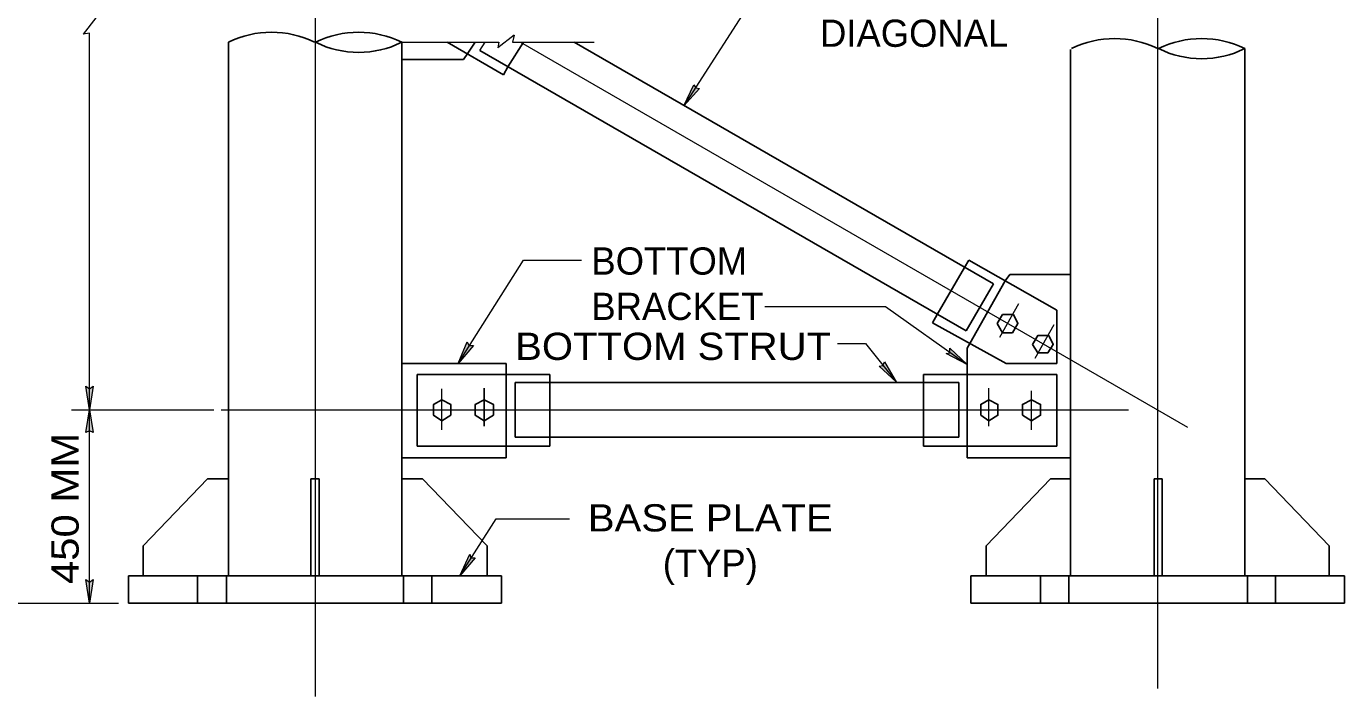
# Model space of a CAD drawing. Extents: x 312601.858 to 312602.699, y 144420.109 to 144420.704.
# Drawn here: x 312601.9345 to 312602.0798, y 144420.3488 to 144420.4227 of the extents above; entities that cross this region are included whole.
import ezdxf
from ezdxf.enums import TextEntityAlignment as Align

# ---------------------------------------------------------------- set-up
doc = ezdxf.new("R2010")
doc.units = 0
doc.header["$LTSCALE"] = 0.0012
for name, pattern in [('DOT_DASHED', [7.7, 5, -1.2, 0.3, -1.2]), ('LONG_DASHED', [7.5, 6, -1.5]), ('MEDIUM_DASHED', [4.5, 3, -1.5])]:
    doc.linetypes.add(name, pattern=pattern)
for name, color, linetype, lineweight in [('1', 7, 'Continuous', 25), ('2', 7, 'Continuous', 13), ('39', 7, 'Continuous', 13)]:
    doc.layers.add(name, color=color, linetype=linetype, lineweight=lineweight)

msp = doc.modelspace()

# ---------------------------------------------------------------- hatches: boundary and pattern name
at = {"layer": '39'}
for points in [[(312602.0083, 144420.4159), (312602.0087, 144420.4158), (312602.007, 144420.4139), (312602.0081, 144420.4162)], [(312601.9833, 144420.3875), (312601.9838, 144420.3875), (312601.9821, 144420.3855), (312601.9831, 144420.3879)], [(312602.0363, 144420.3867), (312602.0363, 144420.3872), (312602.0382, 144420.3854), (312602.0359, 144420.3866)], [(312602.0289, 144420.3853), (312602.0291, 144420.3857), (312602.0304, 144420.3835), (312602.0285, 144420.3852)], [(312601.9415, 144420.3827), (312601.9419, 144420.383), (312601.9415, 144420.3804), (312601.9411, 144420.383)], [(312601.9415, 144420.3827), (312601.9419, 144420.383), (312601.9415, 144420.3804), (312601.9411, 144420.383)], [(312601.9415, 144420.3781), (312601.9411, 144420.3779), (312601.9415, 144420.3804), (312601.9419, 144420.3779)], [(312601.9415, 144420.3781), (312601.9411, 144420.3779), (312601.9415, 144420.3804), (312601.9419, 144420.3779)], [(312601.9835, 144420.3641), (312601.984, 144420.3641), (312601.9823, 144420.3621), (312601.9834, 144420.3645)], [(312601.9835, 144420.3641), (312601.984, 144420.3641), (312601.9823, 144420.3621), (312601.9834, 144420.3645)], [(312601.9415, 144420.3614), (312601.9419, 144420.3617), (312601.9415, 144420.3591), (312601.9411, 144420.3617)], [(312601.9415, 144420.3614), (312601.9419, 144420.3617), (312601.9415, 144420.3591), (312601.9411, 144420.3617)]]:
    msp.add_hatch(color=256, dxfattribs=at).paths.add_polyline_path(points)

# ---------------------------------------------------------------- linework, layer by layer
at = {"layer": '1', "lineweight": 13}
for p, q in [((312601.9422, 144420.4236), (312601.9408, 144420.4218)), ((312601.9415, 144420.4219), (312601.9408, 144420.4218)), ((312601.9415, 144420.3804), (312601.9415, 144420.4219)), ((312601.9883, 144420.4217), (312601.9865, 144420.4203)), ((312601.9883, 144420.4217), (312601.9881, 144420.4209)), ((312601.9759, 144420.4209), (312601.9866, 144420.4209)), ((312601.9845, 144420.42), (312601.9851, 144420.4209)), ((312601.9866, 144420.4209), (312601.9865, 144420.4203)), ((312601.9881, 144420.4209), (312601.9971, 144420.4209)), ((312601.9821, 144420.3855), (312601.9893, 144420.3969)), ((312601.9893, 144420.3969), (312601.9957, 144420.3969)), ((312602.0159, 144420.3918), (312602.0292, 144420.3918)), ((312602.0292, 144420.3918), (312602.0382, 144420.3854)), ((312601.9395, 144420.3804), (312601.9552, 144420.3804)), ((312601.9415, 144420.3591), (312601.9415, 144420.3804)), ((312601.9155, 144420.3591), (312601.9447, 144420.3591))]:
    msp.add_line(p, q, dxfattribs=at)
at = {"layer": '1'}
for p, q in [((312601.9568, 144420.3621), (312601.9568, 144420.4209)), ((312601.9759, 144420.3621), (312601.9759, 144420.4209)), ((312601.9809, 144420.4209), (312601.9871, 144420.4173)), ((312601.9827, 144420.419), (312601.9832, 144420.4197)), ((312602.0381, 144420.3891), (312601.9845, 144420.42)), ((312602.0411, 144420.3943), (312601.9949, 144420.4209)), ((312602.0496, 144420.3621), (312602.0496, 144420.4201)), ((312602.0688, 144420.3621), (312602.0688, 144420.4202)), ((312601.9759, 144420.419), (312601.9827, 144420.419)), ((312601.9871, 144420.4173), (312601.9876, 144420.4182)), ((312602.0384, 144420.3969), (312602.0379, 144420.3961)), ((312602.0384, 144420.3969), (312602.0481, 144420.3914)), ((312602.0429, 144420.3953), (312602.0424, 144420.3946)), ((312602.0496, 144420.3953), (312602.0429, 144420.3953)), ((312602.0411, 144420.3943), (312602.0381, 144420.3891)), ((312602.0349, 144420.3909), (312602.0344, 144420.39)), ((312602.0481, 144420.3914), (312602.0481, 144420.3855)), ((312602.0425, 144420.3855), (312602.0344, 144420.39)), ((312602.0385, 144420.3877), (312602.0382, 144420.3872)), ((312602.0382, 144420.3872), (312602.0382, 144420.3843)), ((312601.976, 144420.3855), (312601.9874, 144420.3855)), ((312601.9874, 144420.3855), (312601.9874, 144420.3843)), ((312602.0481, 144420.3855), (312602.0425, 144420.3855)), ((312601.9776, 144420.3843), (312601.9922, 144420.3843)), ((312601.9776, 144420.3764), (312601.9776, 144420.3843)), ((312601.9884, 144420.3834), (312602.0373, 144420.3834)), ((312601.9884, 144420.3834), (312601.9884, 144420.3774)), ((312601.9922, 144420.3843), (312601.9922, 144420.3834)), ((312602.0481, 144420.3843), (312602.0334, 144420.3843)), ((312602.0334, 144420.3843), (312602.0334, 144420.3834)), ((312602.0373, 144420.3834), (312602.0373, 144420.3774)), ((312602.0481, 144420.3764), (312602.0481, 144420.3843)), ((312601.9776, 144420.3764), (312601.9922, 144420.3764)), ((312601.9874, 144420.3764), (312601.9874, 144420.3751)), ((312601.9884, 144420.3774), (312602.0373, 144420.3774)), ((312601.9922, 144420.3774), (312601.9922, 144420.3764)), ((312602.0334, 144420.3774), (312602.0334, 144420.3764)), ((312602.0481, 144420.3764), (312602.0334, 144420.3764)), ((312602.0382, 144420.3764), (312602.0382, 144420.3751)), ((312601.9759, 144420.3751), (312601.9874, 144420.3751)), ((312602.0496, 144420.3751), (312602.0382, 144420.3751)), ((312601.9474, 144420.3654), (312601.9545, 144420.3728)), ((312601.9545, 144420.3728), (312601.9568, 144420.3728)), ((312601.9659, 144420.3728), (312601.9659, 144420.3621)), ((312601.9659, 144420.3728), (312601.9668, 144420.3728)), ((312601.9668, 144420.3728), (312601.9668, 144420.3621)), ((312601.9782, 144420.3728), (312601.9759, 144420.3728)), ((312601.9853, 144420.3654), (312601.9782, 144420.3728)), ((312602.0403, 144420.3654), (312602.0474, 144420.3728)), ((312602.0474, 144420.3728), (312602.0496, 144420.3728)), ((312602.0588, 144420.3728), (312602.0588, 144420.3621)), ((312602.0597, 144420.3728), (312602.0588, 144420.3728)), ((312602.0597, 144420.3728), (312602.0597, 144420.3621)), ((312601.9474, 144420.3621), (312601.9474, 144420.3654)), ((312601.9853, 144420.3621), (312601.9853, 144420.3654)), ((312602.0403, 144420.3621), (312602.0403, 144420.3654)), ((312602.0781, 144420.3621), (312602.0781, 144420.3654)), ((312601.9458, 144420.3621), (312601.9869, 144420.3621)), ((312601.9458, 144420.3591), (312601.9458, 144420.3621)), ((312601.9869, 144420.3591), (312601.9869, 144420.3621)), ((312602.0798, 144420.3621), (312602.0386, 144420.3621)), ((312602.0386, 144420.3591), (312602.0386, 144420.3621)), ((312602.0798, 144420.3591), (312602.0798, 144420.3621)), ((312601.9458, 144420.3591), (312601.9869, 144420.3591)), ((312602.0798, 144420.3591), (312602.0386, 144420.3591))]:
    msp.add_line(p, q, dxfattribs=at)
at = {"layer": '1', "linetype": 'MEDIUM_DASHED'}
for p, q in [((312601.9832, 144420.4197), (312601.984, 144420.4209)), ((312601.9876, 144420.4182), (312601.9893, 144420.4209)), ((312602.0379, 144420.3961), (312602.0349, 144420.3909)), ((312602.0385, 144420.3877), (312602.0424, 144420.3946)), ((312601.9874, 144420.3843), (312601.9874, 144420.3764)), ((312601.9922, 144420.3834), (312601.9922, 144420.3774)), ((312602.0334, 144420.3834), (312602.0334, 144420.3774)), ((312602.0382, 144420.3843), (312602.0382, 144420.3764))]:
    msp.add_line(p, q, dxfattribs=at)
at = {"layer": '1', "linetype": 'DOT_DASHED', "lineweight": 13}
for p, q in [((312601.989, 144420.4209), (312602.0625, 144420.3785)), ((312602.0418, 144420.3884), (312602.0439, 144420.3921)), ((312602.0457, 144420.3861), (312602.0478, 144420.3898)), ((312601.9803, 144420.3782), (312601.9803, 144420.3827)), ((312602.0406, 144420.3786), (312602.0406, 144420.3828)), ((312602.0453, 144420.3782), (312602.0453, 144420.3825)), ((312601.956, 144420.3804), (312602.0634, 144420.3804))]:
    msp.add_line(p, q, dxfattribs=at)
at = {"layer": '1', "linetype": 'DOT_DASHED'}
msp.add_line((312601.985, 144420.3786), (312601.985, 144420.3828), dxfattribs=at)
at = {"layer": '1', "linetype": 'LONG_DASHED'}
for p, q in [((312601.9534, 144420.3621), (312601.9534, 144420.3591)), ((312601.9566, 144420.3621), (312601.9566, 144420.3591)), ((312601.9761, 144420.3621), (312601.9761, 144420.3591)), ((312601.9792, 144420.3621), (312601.9792, 144420.3591)), ((312602.0463, 144420.3621), (312602.0463, 144420.3591)), ((312602.0494, 144420.3621), (312602.0494, 144420.3591)), ((312602.0691, 144420.3621), (312602.0691, 144420.3591)), ((312602.0722, 144420.3621), (312602.0722, 144420.3591))]:
    msp.add_line(p, q, dxfattribs=at)
at = {"layer": '1', "lineweight": 13}
for points in [[(312602.021, 144420.427), (312602.0154, 144420.427), (312602.007, 144420.4139)], [(312602.0239, 144420.3877), (312602.027, 144420.3877), (312602.0304, 144420.3835)], [(312601.9823, 144420.3621), (312601.9863, 144420.3684), (312601.9944, 144420.3684)]]:
    msp.add_lwpolyline(points, dxfattribs=at)
at = {"layer": '1'}
for points in [[(312602.0415, 144420.3899), (312602.0421, 144420.3909), (312602.0433, 144420.3909), (312602.0438, 144420.3899), (312602.0432, 144420.3889), (312602.0421, 144420.3889)], [(312602.0454, 144420.3876), (312602.046, 144420.3886), (312602.0472, 144420.3886), (312602.0477, 144420.3876), (312602.0471, 144420.3867), (312602.046, 144420.3867)], [(312601.9813, 144420.3798), (312601.9813, 144420.381), (312601.9803, 144420.3815), (312601.9794, 144420.381), (312601.9794, 144420.3798), (312601.9803, 144420.3792)], [(312601.986, 144420.3798), (312601.986, 144420.381), (312601.985, 144420.3815), (312601.984, 144420.381), (312601.984, 144420.3798), (312601.985, 144420.3792)], [(312602.0397, 144420.3798), (312602.0397, 144420.381), (312602.0406, 144420.3815), (312602.0416, 144420.381), (312602.0416, 144420.3798), (312602.0406, 144420.3792)], [(312602.0443, 144420.3798), (312602.0443, 144420.381), (312602.0453, 144420.3815), (312602.0463, 144420.381), (312602.0463, 144420.3798), (312602.0453, 144420.3792)]]:
    msp.add_lwpolyline(points, close=True, dxfattribs=at)
msp.add_lwpolyline([(312602.0781, 144420.3654), (312602.071, 144420.3728), (312602.0688, 144420.3728)], dxfattribs=at)
at = {"layer": '2', "linetype": 'DOT_DASHED'}
for p, q in [((312601.9664, 144420.3488), (312601.9664, 144420.631)), ((312602.0592, 144420.3497), (312602.0592, 144420.6313))]:
    msp.add_line(p, q, dxfattribs=at)
at = {"layer": '2', "lineweight": 25}
for centre, start, end in [((312601.96155, 144420.411286), 63.70649, 116.29351), ((312601.97115, 144420.411286), 63.70649, 116.29351), ((312602.05445, 144420.410586), 63.70649, 116.29351), ((312602.06405, 144420.410586), 63.70649, 116.29351), ((312601.97115, 144420.430514), 243.70649, 296.29351), ((312602.06405, 144420.429814), 243.70649, 296.29351)]:
    msp.add_arc(centre, 0.010723, start, end, dxfattribs=at)
at = {"layer": '39'}
for points in [[(312602.0083, 144420.4159), (312602.0087, 144420.4158), (312602.007, 144420.4139), (312602.0081, 144420.4162)], [(312601.9833, 144420.3875), (312601.9838, 144420.3875), (312601.9821, 144420.3855), (312601.9831, 144420.3879)], [(312602.0363, 144420.3867), (312602.0363, 144420.3872), (312602.0382, 144420.3854), (312602.0359, 144420.3866)], [(312602.0289, 144420.3853), (312602.0291, 144420.3857), (312602.0304, 144420.3835), (312602.0285, 144420.3852)], [(312601.9415, 144420.3827), (312601.9419, 144420.383), (312601.9415, 144420.3804), (312601.9411, 144420.383)], [(312601.9415, 144420.3827), (312601.9419, 144420.383), (312601.9415, 144420.3804), (312601.9411, 144420.383)], [(312601.9415, 144420.3781), (312601.9411, 144420.3779), (312601.9415, 144420.3804), (312601.9419, 144420.3779)], [(312601.9415, 144420.3781), (312601.9411, 144420.3779), (312601.9415, 144420.3804), (312601.9419, 144420.3779)], [(312601.9835, 144420.3641), (312601.984, 144420.3641), (312601.9823, 144420.3621), (312601.9834, 144420.3645)], [(312601.9835, 144420.3641), (312601.984, 144420.3641), (312601.9823, 144420.3621), (312601.9834, 144420.3645)], [(312601.9415, 144420.3614), (312601.9419, 144420.3617), (312601.9415, 144420.3591), (312601.9411, 144420.3617)], [(312601.9415, 144420.3614), (312601.9419, 144420.3617), (312601.9415, 144420.3591), (312601.9411, 144420.3617)]]:
    msp.add_lwpolyline(points, close=True, dxfattribs=at)

# ---------------------------------------------------------------- texts
at = {"layer": '2'}
for s, p in [('DIAGONAL', (312602.022, 144420.4204)), ('BOTTOM', (312601.9968, 144420.3953)), ('BRACKET', (312601.9968, 144420.3903))]:
    msp.add_text(s, height=0.003, dxfattribs=at).set_placement(p)
at = {"layer": '2', "width": 1.1}
msp.add_text('BOTTOM STRUT', height=0.003, dxfattribs=at).set_placement((312601.9884, 144420.3859))
at = {"layer": '2', "width": 1.15}
msp.add_text('450 MM', height=0.003, rotation=90, dxfattribs=at).set_placement((312601.9403, 144420.3612))
at = {"layer": '2', "width": 1.1}
msp.add_text('BASE PLATE', height=0.003, dxfattribs=at).set_placement((312602.0099, 144420.367), align=Align.CENTER)
at = {"layer": '2'}
msp.add_text('(TYP)', height=0.003, dxfattribs=at).set_placement((312602.0099, 144420.362), align=Align.CENTER)

doc.saveas('drawing.dxf')
